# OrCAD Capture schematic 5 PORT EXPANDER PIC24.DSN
size D; title: 5 POER EXPANDER BOARD; rev: C
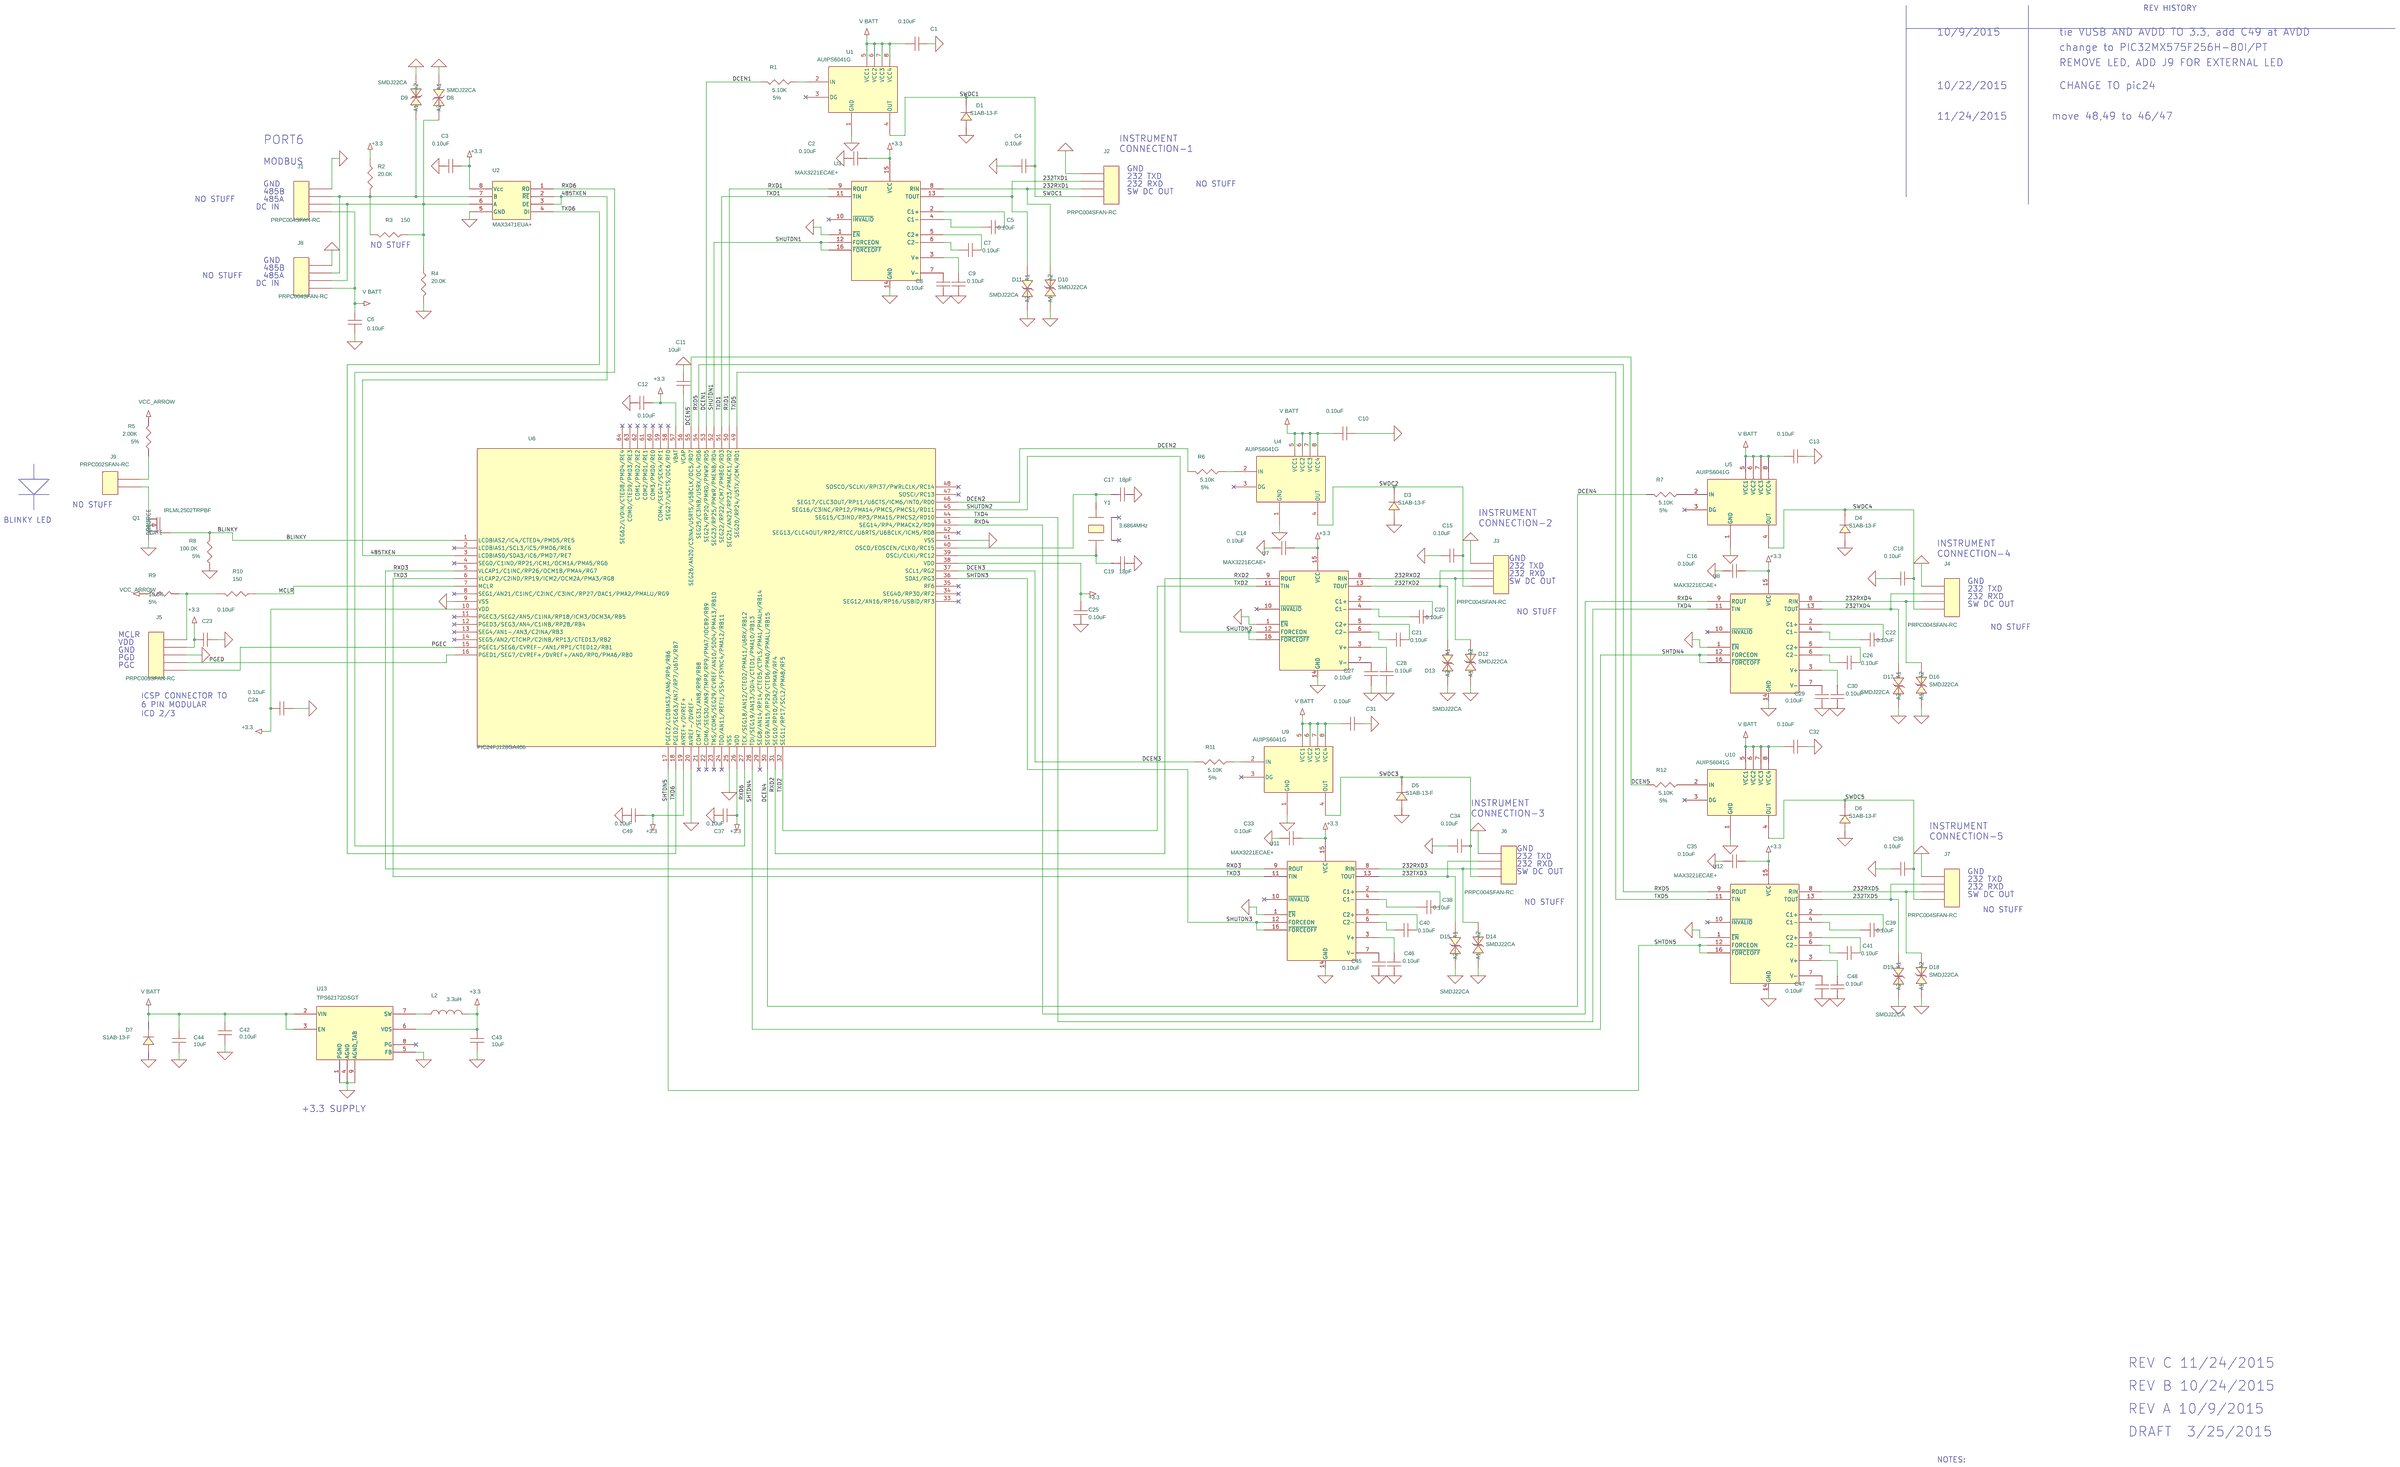
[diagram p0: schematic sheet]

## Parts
C1  0.10uF  [CAPC2012X100N]
C2  0.10uF  [CAPC2012X100N]
C3  0.10uF  [CAPC2012X100N]
C4  0.10uF  [CAPC2012X100N]
C5  0.10uF  [CAPC2012X100N]
C6  0.10uF  [CAPC2012X100N]
C7  0.10uF  [CAPC2012X100N]
C8  0.10uF  [CAPC2012X100N]
C9  0.10uF  [CAPC2012X100N]
C10  0.10uF  [CAPC2012X100N]
C11  10uF  [CAPC3216X180N]
C12  0.10uF  [CAPC2012X100N]
C13  0.10uF  [CAPC2012X100N]
C14  0.10uF  [CAPC2012X100N]
C15  0.10uF  [CAPC2012X100N]
C16  0.10uF  [CAPC2012X100N]
C17  18pF  [CAPC2012X88N]
C18  0.10uF  [CAPC2012X100N]
C19  18pF  [CAPC2012X88N]
C20  0.10uF  [CAPC2012X100N]
C21  0.10uF  [CAPC2012X100N]
C22  0.10uF  [CAPC2012X100N]
C23  0.10uF  [CAPC2012X100N]
C24  0.10uF  [CAPC2012X100N]
C25  0.10uF  [CAPC2012X100N]
C26  0.10uF  [CAPC2012X100N]
C27  0.10uF  [CAPC2012X100N]
C28  0.10uF  [CAPC2012X100N]
C29  0.10uF  [CAPC2012X100N]
C30  0.10uF  [CAPC2012X100N]
C31  0.10uF  [CAPC2012X100N]
C32  0.10uF  [CAPC2012X100N]
C33  0.10uF  [CAPC2012X100N]
C34  0.10uF  [CAPC2012X100N]
C35  0.10uF  [CAPC2012X100N]
C36  0.10uF  [CAPC2012X100N]
C37  0.10uF  [CAPC2012X100N]
C38  0.10uF  [CAPC2012X100N]
C39  0.10uF  [CAPC2012X100N]
C40  0.10uF  [CAPC2012X100N]
C41  0.10uF  [CAPC2012X100N]
C42  0.10uF  [CAPC2012X100N]
C43  10uF  [CAPC4532X220N]
C44  10uF  [CAPC4532X220N]
C45  0.10uF  [CAPC2012X100N]
C46  0.10uF  [CAPC2012X100N]
C47  0.10uF  [CAPC2012X100N]
C48  0.10uF  [CAPC2012X100N]
C49  0.10uF  [CAPC2012X100N]
D1  S1AB-13-F  [DIOM5336X250N]
D3  S1AB-13-F  [DIOM5336X250N]
D4  S1AB-13-F  [DIOM5336X250N]
D5  S1AB-13-F  [DIOM5336X250N]
D6  S1AB-13-F  [DIOM5336X250N]
D7  S1AB-13-F  [DIOM5336X250N]
D8  SMDJ22CA  [DIOMNP7959X262N]
D9  SMDJ22CA  [DIOMNP7959X262N]
D10  SMDJ22CA  [DIOMNP7959X262N]
D11  SMDJ22CA  [DIOMNP7959X262N]
D12  SMDJ22CA  [DIOMNP7959X262N]
D13  SMDJ22CA  [DIOMNP7959X262N]
D14  SMDJ22CA  [DIOMNP7959X262N]
D15  SMDJ22CA  [DIOMNP7959X262N]
D16  SMDJ22CA  [DIOMNP7959X262N]
D17  SMDJ22CA  [DIOMNP7959X262N]
D18  SMDJ22CA  [DIOMNP7959X262N]
D19  SMDJ22CA  [DIOMNP7959X262N]
J1  PRPC004SFAN-RC  [HDRV4W64P254_4X1_1016X254H1363B]
J2  PRPC004SFAN-RC  [HDRV4W64P254_4X1_1016X254H1363B]
J3  PRPC004SFAN-RC  [HDRV4W64P254_4X1_1016X254H1363B]
J4  PRPC004SFAN-RC  [HDRV4W64P254_4X1_1016X254H1363B]
J5  PRPC005SFAN-RC  [HDRV5W64P254_5X1_1270X254H1363B]
J6  PRPC004SFAN-RC  [HDRV4W64P254_4X1_1016X254H1363B]
J7  PRPC004SFAN-RC  [HDRV4W64P254_4X1_1016X254H1363B]
J8  PRPC004SFAN-RC  [HDRV4W64P254_4X1_1016X254H1363B]
J9  PRPC002SFAN-RC  [HDRV2W64P254_2X1_508X254H1363B]
L2  3.3uH  [IND_7443340330]
Q1  IRLML2502TRPBF  [SOT95P237X112-3L20N_132]
R1  5.10K  [RESC2012X50N]
R2  20.0K  [RESC2012X50N]
R3  150  [RESC3216X60N]
R4  20.0K  [RESC2012X50N]
R5  2.00K  [RESC2012X50N]
R6  5.10K  [RESC2012X50N]
R7  5.10K  [RESC2012X50N]
R8  100.0K  [RESC2012X50N]
R9  10.0K  [RESC2012X50N]
R10  150  [RESC3216X60N]
R11  5.10K  [RESC2012X50N]
R12  5.10K  [RESC2012X50N]
U1  AUIPS6041G  [SOIC127P600X175-8L87N]
U2  MAX3471EUA+  [SOP65P490X110-8L25N]
U3  MAX3221ECAE+  [SOP65P777X199-16L32N]
U4  AUIPS6041G  [SOIC127P600X175-8L87N]
U5  AUIPS6041G  [SOIC127P600X175-8L87N]
U6  PIC24FJ128GA406  [QFP50P1200X1200X120-64N]
U7  MAX3221ECAE+  [SOP65P777X199-16L32N]
U8  MAX3221ECAE+  [SOP65P777X199-16L32N]
U9  AUIPS6041G  [SOIC127P600X175-8L87N]
U10  AUIPS6041G  [SOIC127P600X175-8L87N]
U11  MAX3221ECAE+  [SOP65P777X199-16L32N]
U12  MAX3221ECAE+  [SOP65P777X199-16L32N]
U13  TPS62172DSGT  [SON50P200X200X80-9T100X170N]
Y1  3.6864MHz  [OSCL940P460X360X370-4N]

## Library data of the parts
C1-C10 C12-C16 C18 C20-C42 C45-C49 = CAP: CLASS: DISCRETE; Dielectric Type: Ceramic; Manufacturer: Kemet; Manufacturer PN: C0805C104K3RAC; PART_NUMBER: C0805C104K3RAC; Package Size: 0805; Rated Voltage: 25V; Temperature Coefficient: X7R; Tolerance: 10%
C11 = CAP: CAP CER 10UF 16V 10% X7R 1206; CLASS: DISCRETE; Dielectric Type: Ceramic; Manufacturer: Kemet; Manufacturer PN: C1206C106K4RACTU; PART_NUMBER: C1206C106K4RAC; Package Size: 1206; Rated Voltage: 16V; Temperature Coefficient: X7R; Tolerance: 10%
C17 C19 = CAP: CAP CER 18PF 25V 5% NP0 0805; CLASS: DISCRETE; Dielectric Type: Capacitors; Manufacturer: Kemet; Manufacturer PN: C0805C180J3GACTU; PART_NUMBER: C0805C180J3GACTU; Package Size: 0805 (2012 Metric); Rated Voltage: 25V; Temperature Coefficient: C0G, NP0; Tolerance: ±5%
C43 C44 = CAP: CAP CER 10UF 50V Y5V 1812; CLASS: DISCRETE; Dielectric Type: Capacitors; Manufacturer: TDK Corporation; Manufacturer PN: C4532Y5V1H106Z; PART_NUMBER: C4532Y5V1H106Z; Package Size: 1812 (4532 Metric); Rated Voltage: 50V; Temperature Coefficient: Y5V (F); Tolerance: -20%, +80%
D1 D3-D7 = DIODE: DIODE GPP 1A 50V SMB; CLASS: DISCRETE; Manufacturer: Diodes Inc; Package Size: DO-214AA, SMB; Rated Voltage: 1.1V @ 1A
D8-D19 = DIODE_TVS_BI_DIR: TVS DIODE 22VWM 35.5VC SMD; CLASS: DISCRETE; Manufacturer: Littelfuse Inc; Package Size: DO-214AB, SMC
J1-J4 J6-J8 = CON4: CONN HEADER .100" SNGL STR 4POS; CLASS: IO; Manufacturer: Sullins Connector Solutions; Package Size: 0.318" (8.08mm)
J5 = CON5: CONN HEADER .100" SNGL STR 5POS; CLASS: IO; Manufacturer: Sullins Connector Solutions; Package Size: 0.318" (8.08mm)
J9 = CON2: CONN HEADER .100" SNGL STR 2POS; CLASS: IO; Manufacturer: Sullins Connector Solutions; Package Size: 0.318" (8.08mm)
L2 = IND: INDUCTOR POWER 3.3UH 14A SMD; CLASS: DISCRETE; Manufacturer: Wurth Electronics Inc; Manufacturer PN: 7443340330; PART_NUMBER: 7443340330; Package Size: 0.331" L x 0.311" W x 0.283" H (8.40mm x 7.90mm x 7.20mm); Tolerance: ±20%
Q1 = MOSFET_I_EN_GSD_SYM-MOD1: MOSFET N-CH 20V 4.2A SOT-23; CLASS: DISCRETE; Manufacturer: International Rectifier; Package Size: TO-236-3, SC-59, SOT-23-3; Polarity: MOSFET N-Channel, Metal Oxide; Rated Power: 1.25W
R1 R6 R7 R11 R12 = RES: CLASS: DISCRETE; Manufacturer: Vishay; Manufacturer PN: CRCW08055K10JNEA; PART_NUMBER: CRCW08055K10JNEA; Package Size: 0805; Rated Power: 0.125W; Temperature Coefficient: 200ppm/K; Tolerance: 5%
R2 R4 = RES: CLASS: DISCRETE; Manufacturer: Vishay; Manufacturer PN: CRCW080520K0JNEA; PART_NUMBER: CRCW080520K0JNEA; Package Size: 0805; Rated Power: 0.125W; Temperature Coefficient: 200ppm/K; Tolerance: 5%
R3 R10 = RES: CLASS: DISCRETE; Manufacturer: Vishay; Manufacturer PN: CRCW1206150RJNEA; PART_NUMBER: CRCW1206150RJNEA; Package Size: 1206; Rated Power: 0.25W; Temperature Coefficient: 200ppm/K; Tolerance: 5%
R5 = RES: CLASS: DISCRETE; Manufacturer: Vishay; Manufacturer PN: CRCW08052K00JNEA; PART_NUMBER: CRCW08052K00JNEA; Package Size: 0805; Rated Power: 0.125W; Temperature Coefficient: 200ppm/K; Tolerance: 5%
R8 = RES: CLASS: DISCRETE; Manufacturer: Vishay; Manufacturer PN: CRCW0805100KJNEA; PART_NUMBER: CRCW0805100KJNEA; Package Size: 0805; Rated Power: 0.125W; Temperature Coefficient: 200ppm/K; Tolerance: 5%
R9 = RES: CLASS: DISCRETE; Manufacturer: Vishay; Manufacturer PN: CRCW080510K0JNEA; PART_NUMBER: CRCW080510K0JNEA; Package Size: 0805; Rated Power: 0.125W; Temperature Coefficient: 200ppm/K; Tolerance: 5%
U1 U4 U5 U9 U10 = AUIPS6041G: IC SW IPS 1CH HIGH SIDE 8SOIC; CLASS: IC; Manufacturer: International Rectifier; Package Size: 8-SOIC (0.154", 3.90mm Width); Supply Voltage: 6 V ~ 28 V
U2 = MAX3471xUA: IC TXRX DIFF RS485/422 8-UMAX; CLASS: IC; Manufacturer: Maxim Integrated Products; Package Size: 8-TSSOP, 8-MSOP (0.118", 3.00mm Width); Supply Voltage: 2.5 V ~ 5.5 V
U3 U7 U8 U11 U12 = MAX3221E: IC TXRX RS232 250KBPS SD 16-SSOP; CLASS: IC; Manufacturer: Maxim Integrated; Package Size: 16-SSOP (0.209", 5.30mm Width); Supply Voltage: 3 V - 5.5 V
U6 = PIC24FJ128GA406-I_PT
U13 = TPS62172: IC REG BUCK SYNC 3.3V 0.5A 8WSON; CLASS: IC; Manufacturer: Texas Instruments; Package Size: 8-WFDFN Exposed Pad
Y1 = CRYSTAL14_1: CRYSTAL 3.6864 MHZ 18PF SMD; CLASS: DISCRETE; Frequency Stability: 50ppm; Frequency Tolerance: 30ppm; Manufacturer: ECS Inc; Manufacturer PN: ECS-36-18-7SX-TR; PART_NUMBER: ECS-36-18-7SX-TR; Package Size: 0.492" L x 0.180" W (12.50mm x 4.60mm)

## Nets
GND_SIGNAL: C1.1 C2.2 C3.2 C4.2 C6.2 C8.2 C9.2 C10.1 C11.1 C12.2 C13.1 C14.2 C15.2 C16.2 C17.2 C18.2 C19.2 C23.2 C24.2 C25.2 C27.2 C28.2 C29.2 C30.2 C31.1 C32.1 C33.2 C34.2 C35.2 C36.2 C37.1 C42.2 C43.2 C44.2 C45.2 C46.2 C47.2 C48.2 C49.1 D1.A(ANODE) D3.A(ANODE) D4.A(ANODE) D5.A(ANODE) D6.A(ANODE) D7.A(ANODE) D8.1(A1) D9.2(A2) D10.1(A1) D11.2(A2) D12.1(A1) D13.2(A2) D14.1(A1) D15.2(A2) D16.1(A1) D17.2(A2) D18.1(A1) D19.2(A2) J1.1 J2.1 J3.1 J4.1 J5.3 J6.1 J7.1 J8.1 Q1.2(SOURCE) R4.2 R8.2 U1.1(GND) U2.5(GND) U3.1(~{EN}) U3.14(GND) U4.1(GND) U5.1(GND) U6.9(VSS) U6.20(AVREF-/DVREF-) U6.25(VSS) U6.41(VSS) U7.1(~{EN}) U7.14(GND) U8.1(~{EN}) U8.14(GND) U9.1(GND) U10.1(GND) U11.1(~{EN}) U11.14(GND) U12.1(~{EN}) U12.14(GND) U13.1(PGND) U13.4(AGND) U13.5(FB) U13.9(AGND_TAB)
232RXD1: D10.2(A2) J2.3 U3.8(RIN)
232RXD2: D12.2(A2) J3.3 U7.8(RIN)
232RXD3: D14.2(A2) J6.3 U11.8(RIN)
232RXD4: D16.2(A2) J4.3 U8.8(RIN)
232RXD5: D18.2(A2) J7.3 U12.8(RIN)
232TXD1: D11.1(A1) J2.2 U3.13(TOUT)
232TXD2: D13.1(A1) J3.2 U7.13(TOUT)
232TXD3: D15.1(A1) J6.2 U11.13(TOUT)
232TXD4: D17.1(A1) J4.2 U8.13(TOUT)
232TXD5: D19.1(A1) J7.2 U12.13(TOUT)
485TXEN: U2.2(~{RE}) U2.3(DE) U6.3(LCDBIAS0/SDA3/IC6/PMD7/RE7)
+3.3: C2.1 C3.1 C12.1 C14.1 C16.1 C23.1 C24.1 C25.1 C33.1 C35.1 C37.2 C43.1 C49.2 J5.2 L2.2 R2.1 R9.1 U2.8(Vcc) U3.15(VCC) U6.10(VDD) U6.19(AVREF+/DVREF+) U6.26(VDD) U6.38(VDD) U6.57(VBAT) U7.15(VCC) U8.15(VCC) U11.15(VCC) U12.15(VCC) U13.6(VOS)
BLINKY: Q1.1(GATE) R8.1 U6.1(LCDBIAS2/IC4/CTED4/PMD5/RE5)
DCEN1: R1.2 U6.53(SEG24/RP20/PMRD/PMWR/RD5)
DCEN2: R6.2 U6.46(SEG17/CLC3OUT/RP11/U6CTS/ICM6/INT0/RD0)
DCEN3: R11.2 U6.37(SCL1/RG2)
DCEN4: R7.2 U6.30(SEG9/AN15/RP29/CTED6/PMA0/PMALL/RB15)
DCEN5: R12.2 U6.55(SEG26/AN20/C3INA/U5RTS/U5BCLK/OC5/RD7)
MCLR: R10.1 U6.7(MCLR)
PGEC: J5.5 U6.15(PGEC1/SEG6/CVREF-/AN1/RP1/CTED12/RB1)
PGED: J5.4 U6.16(PGED1/SEG7/CVREF+/DVREF+/AN0/RP0/PMA6/RB0)
RXD1: U3.9(ROUT) U6.50(SEG21/AN23/RP23/PMACK1/RD2)
RXD2: U6.31(SEG10/RP10/SDA2/PMA9/RF4) U7.9(ROUT)
RXD3: U6.5(VLCAP1/C1INC/RP26/OCM1B/PMA4/RG7) U11.9(ROUT)
RXD4: U6.43(SEG14/RP4/PMACK2/RD9) U8.9(ROUT)
RXD5: U6.54(SEG25/C3INB/U5RX/OC4/RD6) U12.9(ROUT)
RXD6: U2.1(RO) U6.27(TCK/SEG18/AN12/CTED2/PMA11/U6RX/RB12)
SHTDN3: U6.36(SDA1/RG3) U11.12(FORCEON) U11.16(~{FORCEOFF})
SHTDN4: U6.28(TDI/SEG19/AN13/SDI4/CTED1/PMA10/RB13) U8.12(FORCEON) U8.16(~{FORCEOFF})
SHTDN5: U6.17(PGEC2/LCDBIAS3/AN6/RP6/RB6) U12.12(FORCEON) U12.16(~{FORCEOFF})
SHUTDN1: U3.12(FORCEON) U3.16(~{FORCEOFF}) U6.52(SEG23/RP25/PMWR/PMENB/RD4)
SHUTDN2: U6.45(SEG16/C3INC/RP12/PMA14/PMCS/PMCS1/RD11) U7.12(FORCEON) U7.16(~{FORCEOFF})
SWDC1: C4.1 D1.C(CATHODE) J2.4 U1.4(OUT)
SWDC2: C15.1 D3.C(CATHODE) J3.4 U4.4(OUT)
SWDC3: C34.1 D5.C(CATHODE) J6.4 U9.4(OUT)
SWDC4: C18.1 D4.C(CATHODE) J4.4 U5.4(OUT)
SWDC5: C36.1 D6.C(CATHODE) J7.4 U10.4(OUT)
TXD1: U3.11(TIN) U6.51(SEG22/RP22/ICM7/PMBE0/RD3)
TXD2: U6.32(SEG11/RP17/SCL2/PMA8/RF5) U7.11(TIN)
TXD3: U6.6(VLCAP2/C2IND/RP19/ICM2/OCM2A/PMA3/RG8) U11.11(TIN)
TXD4: U6.44(SEG15/C3IND/RP3/PMA15/PMCS2/RD10) U8.11(TIN)
TXD5: U6.49(SEG20/RP24/U5TX/ICM4/RD1) U12.11(TIN)
TXD6: U2.4(DI) U6.18(PGED2/SEG63/AN7/RP7/U6TX/RB7)
V Batt: C1.2 C6.1 C10.2 C13.2 C31.2 C32.2 C42.1 C44.1 D7.C(CATHODE) J1.4 J8.4 R5.1 U1.5(VCC1) U1.6(VCC2) U1.7(VCC3) U1.8(VCC4) U4.5(VCC1) U4.6(VCC2) U4.7(VCC3) U4.8(VCC4) U5.5(VCC1) U5.6(VCC2) U5.7(VCC3) U5.8(VCC4) U9.5(VCC1) U9.6(VCC2) U9.7(VCC3) U9.8(VCC4) U10.5(VCC1) U10.6(VCC2) U10.7(VCC3) U10.8(VCC4) U13.2(VIN) U13.3(EN)
N2131735: J5.1 R9.2 R10.2
N2260858: C17.1 U6.40(OSCO/EOSCEN/CLKO/RC15) Y1.1
N2261357: C19.1 U6.39(OSCI/CLKI/RC12) Y1.4
N2278775: J9.2 Q1.3(DRAIN)
N2747669: D9.1(A1) J1.2 J8.2 R2.2 R3.2 U2.7(B)
N2747673: D8.2(A2) J1.3 J8.3 R3.1 R4.1 U2.6(A)
N2750504: R1.1 U1.2(IN)
N2750508: C5.1 U3.2(C1+)
N2750516: C5.2 U3.4(C1-)
N2750524: C7.1 U3.5(C2+)
N2750528: C7.2 U3.6(C2-)
N2750540: C9.1 U3.3(V+)
N2752523: C22.1 U8.2(C1+)
N2752547: C22.2 U8.4(C1-)
N2752555: C26.1 U8.5(C2+)
N2752559: C26.2 U8.6(C2-)
N2752571: C30.1 U8.3(V+)
N2754000: C39.1 U12.2(C1+)
N2754024: C39.2 U12.4(C1-)
N2754032: C41.1 U12.5(C2+)
N2754036: C41.2 U12.6(C2-)
N2754048: C48.1 U12.3(V+)
N2759256: R6.1 U4.2(IN)
N2759260: C20.1 U7.2(C1+)
N2759288: C20.2 U7.4(C1-)
N2759296: C21.1 U7.5(C2+)
N2759300: C21.2 U7.6(C2-)
N2759312: C28.1 U7.3(V+)
N2759820: R11.1 U9.2(IN)
N2759832: C38.1 U11.2(C1+)
N2759856: C38.2 U11.4(C1-)
N2759864: C40.1 U11.5(C2+)
N2759868: C40.2 U11.6(C2-)
N2759880: C46.1 U11.3(V+)
N3717555: L2.1 U13.7(SW)
N3738792: J9.1 R5.2
N3757845: C11.2 U6.56(VCAP)
N3798094: R7.1 U5.2(IN)
N3798095: R12.1 U10.2(IN)
N3798097: C8.1 U3.7(V-)
N3798098: C27.1 U7.7(V-)
N3798099: C29.1 U8.7(V-)
N3798100: C47.1 U12.7(V-)
N3798102: C45.1 U11.7(V-)

Not connected (* = marked no-connect by the designer): U1 3(DG)*; U3 10(~{INVALID})*; U4 3(DG)*; U5 3(DG)*; U6 2(LCDBIAS1/SCL3/IC5/PMD6/RE6)* 4(SEG0/C1IND/RP21/ICM1/OCM1A/PMA5/RG6)* 8(SEG1/AN21/C1INC/C2INC/C3INC/RP27/DAC1/PMA2/PMALU/RG9)* 11(PGEC3/SEG2/AN5/C1INA/RP18/ICM3/OCM3A/RB5)* 12(PGED3/SEG3/AN4/C1INB/RP28/RB4)* 13(SEG4/AN1-/AN3/C2INA/RB3)* 14(SEG5/AN2/CTCMP/C2INB/RP13/CTED13/RB2)* 21(COM7/SEG31/AN8/RP8/RB8)* 22(COM6/SEG30/AN9/TMPR/RP9/PMA7/IOCB9/RB9)* 23(TMS/COM5/SEG29/CVREF/AN10/SDO4/PMA13/RB10)* 24(TDO/AN11/REFI1/SS4/FSYNC4/PMA12/RB11)* 29(SEG8/AN14/RP14/CTED5/CTPLS/PMA1/PMALH/RB14)* 33(SEG12/AN16/RP16/USBID/RF3)* 34(SEG40/RP30/RF2)* 35(RF6)* 42(SEG13/CLC4OUT/RP2/RTCC/U6RTS/U6BCLK/ICM5/RD8)* 47(SOSCI/RC13)* 48(SOSCO/SCLKI/RPI37/PWRLCLK/RC14)* 58(SEG27/U5CTS/OC6/RF0)* 59(COM4/SEG47/SCK4/RF1)* 60(COM3/PMD0/RE0)* 61(COM2/PMD1/RE1)* 62(COM1/PMD2/RE2)* 63(COM0/CTED9/PMD3/RE3)* 64(SEG62/LVDIN/CTED8/PMD4/RE4)*; U7 10(~{INVALID})*; U8 10(~{INVALID})*; U9 3(DG)*; U10 3(DG)*; U11 10(~{INVALID})*; U12 10(~{INVALID})*; U13 8(PG)*; Y1 2* 3*

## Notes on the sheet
- REV HISTORY
- 10/9/2015
- tie VUSB AND AVDD TO 3.3, add C49 at AVDD
- change to PIC32MX575F256H-80I/PT
- REMOVE LED, ADD J9 FOR EXTERNAL LED
- 10/22/2015
- CHANGE TO pic24
- 11/24/2015
- move 48,49 to 46/47
- PORT6
- INSTRUMENT
  CONNECTION-1
- MODBUS
- GND
- 232 TXD
- 485B
- GND
- 232 RXD
- SW DC OUT
- NO STUFF
- NO STUFF
- 485A
- DC IN
- NO STUFF
- GND
- 485B
- NO STUFF
- 485A
- DC IN
- NO STUFF
- INSTRUMENT
  CONNECTION-2
- BLINKY LED
- INSTRUMENT
  CONNECTION-4
- GND
- 232 TXD
- 232 RXD
- SW DC OUT
- 232 TXD
- GND
- 232 RXD
- SW DC OUT
- NO STUFF
- NO STUFF
- MCLR
- VDD
- GND
- PGD
- PGC
- ICSP CONNECTOR TO
  6 PIN MODULAR
  ICD 2/3
- INSTRUMENT
  CONNECTION-3
- INSTRUMENT
  CONNECTION-5
- GND
- 232 TXD
- 232 RXD
- SW DC OUT
- GND
- 232 RXD
- 232 TXD
- SW DC OUT
- NO STUFF
- NO STUFF
- +3.3 SUPPLY
- REV C 11/24/2015
- REV B 10/24/2015
- REV A 10/9/2015
- DRAFT  3/25/2015
- NOTES:
